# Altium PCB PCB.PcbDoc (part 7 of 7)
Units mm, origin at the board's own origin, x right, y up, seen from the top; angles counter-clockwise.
Board outline 243.2 x 142.8 mm, 4 copper layers (Top Layer, Layer 1, Layer 2, Bottom Layer), stack 0.603 mm thick; 451 components, 380 nets, 2276 pads, 1520 vias.
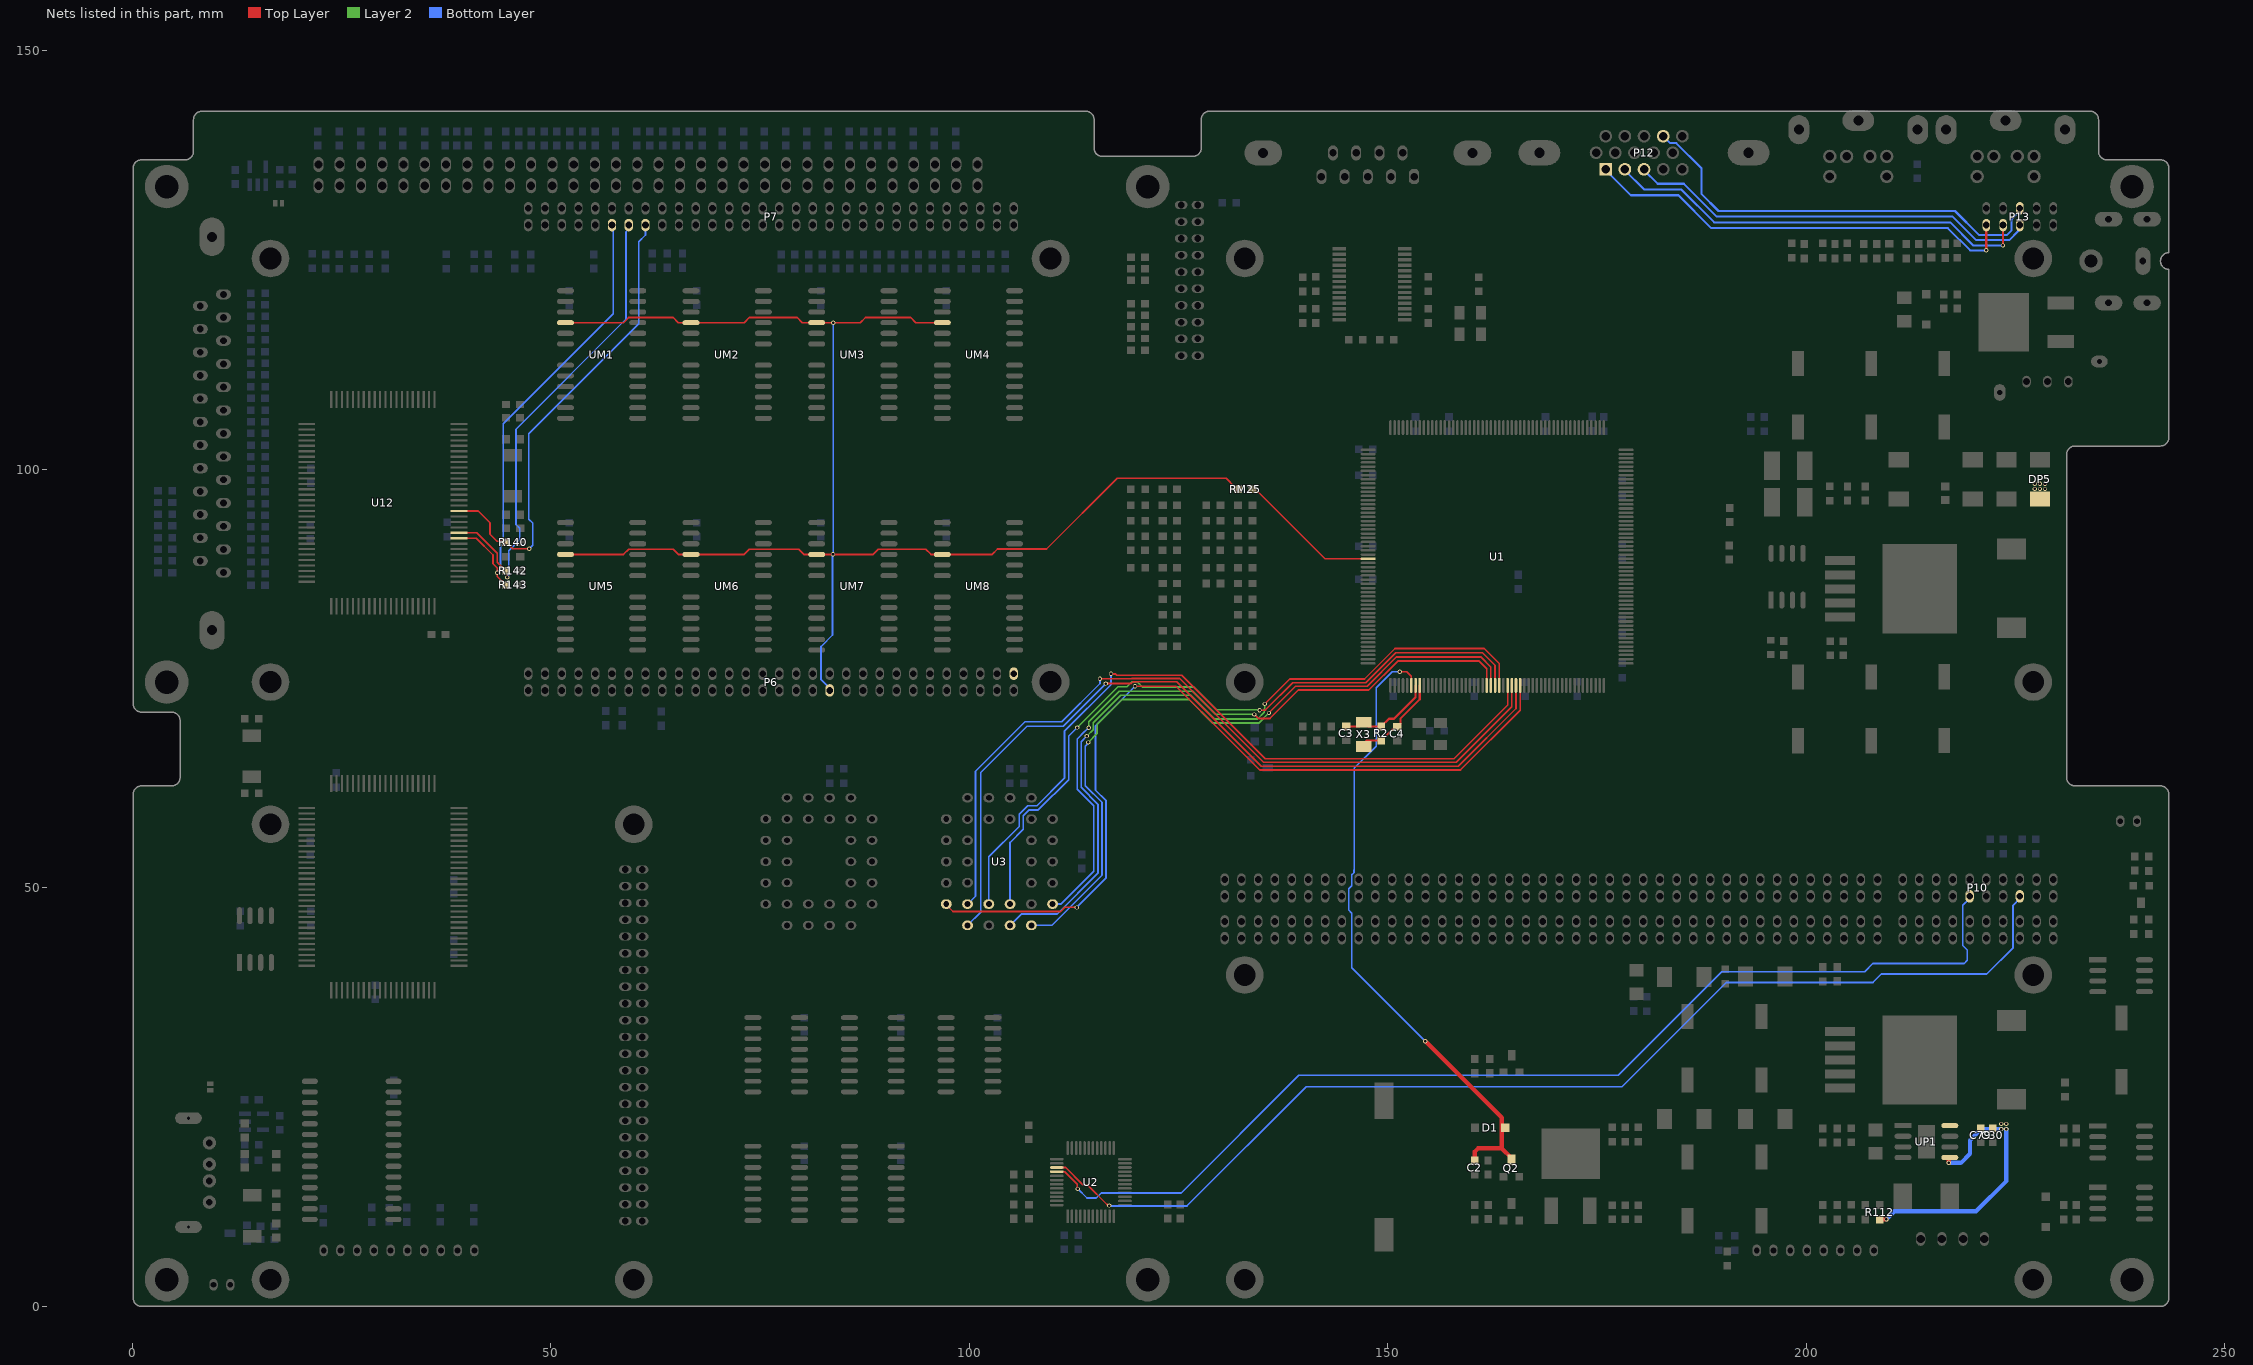
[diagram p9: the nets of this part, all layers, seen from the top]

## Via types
v1: diameter 0.508, hole 0.305, Top Layer to Bottom Layer, tented both sides, 1451 vias
v2: diameter 0.508, hole 0.3, Top Layer to Bottom Layer, 67 vias
v3: diameter 1.2, hole 1.2, Top Layer to Bottom Layer, 2 vias

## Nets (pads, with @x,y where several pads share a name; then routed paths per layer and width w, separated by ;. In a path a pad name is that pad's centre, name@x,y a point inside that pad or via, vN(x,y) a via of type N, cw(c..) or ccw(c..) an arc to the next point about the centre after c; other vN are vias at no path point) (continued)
VCHG: C30.1 C79.1 DP5.K P6.60 R112.1 UP1.5 UP1.8 | length 32.9
  Top Layer w0.508: R112.1@208.748,10.406 208.75,10.404 v1(209.561,10.404) ; v1(217.003,17.161) 217.003,17.749 217.05,17.796 UP1.5@217.13,17.796
  Bottom Layer w0.508: v1(209.561,10.404) 210.526,11.369 220.255,11.369 223.887,15.002 v1(223.887,21.199) ; v1(217.003,17.161) 218.451,17.161 219.543,18.253 219.543,19.853 220.89,21.199 v1(223.277,21.199)
  other v1: 223.277,21.809 223.887,21.809 227.29,97.678 227.9,97.678 228.51,97.678 227.29,98.287 227.9,98.287 228.51,98.287
VCMOS: C2.1 D1.K Q2.C U1.110 | length 76.6
  Top Layer w0.203: v1(151.421,75.835) 152.233,75.835 152.786,75.282 152.786,74.224 U1.110@152.805,74.206
  Top Layer w0.508: v1(154.457,31.699) 163.6,22.557 163.6,18.888 ; C2.1@160.339,17.487 C2.1@160.387,17.44 160.387,18.511 160.764,18.888 163.6,18.888 ; Q2.C@164.768,17.542 164.768,17.719 163.6,18.888
  Bottom Layer w0.203: v1(151.421,75.835) 150.506,75.835 148.601,73.93 148.601,66.945 145.985,64.328 145.985,52.187 145.96,52.162 145.96,51.848 145.695,51.583 145.695,50.268 145.314,49.887 145.314,47.363 145.686,46.991 145.686,40.471 v1(154.457,31.699)
VGA_B_OUT: P12.3 P13.5 | length 49.4
  Bottom Layer w0.254: P12.3@180.6,135.76 182.232,134.128 185.355,134.128 189.279,130.204 217.473,130.204 220.28,127.397 224.217,127.397 225.277,128.456 225.277,128.502 225.376,128.602 225.376,129.076 P13.5@225.5,129.2
VGA_G_OUT: P12.2 P13.3 | length 51.3
  Top Layer w0.254: v1(223.48,126.762) 223.49,126.771 223.49,129.19 P13.3@223.5,129.2
  Bottom Layer w0.254: P12.2@178.31,135.76 180.628,133.442 185.05,133.442 188.971,129.521 217.19,129.521 219.95,126.762 v1(223.48,126.762)
VGA_IN_EN#: P10.6 U2.3 | length 135.3
  Top Layer w0.203: U2.3@110.431,16.603 111.515,16.603 113.563,14.554 114.071,14.554 116.447,12.179 116.506,12.179 116.627,12.058 v1(116.71,12.058)
  Bottom Layer w0.203: v1@116.762,12.014 126.007,12.014 140.257,26.264 177.978,26.264 190.424,38.71 207.948,38.71 208.964,39.726 221.56,39.726 224.695,42.861 224.695,47.945 225.5,48.75 P10.6@225.5,49
VGA_R_OUT: P12.1 P13.1 | length 52.5
  Top Layer w0.254: v1(221.474,126.177) 221.487,126.19 221.487,129.187 P13.1@221.5,129.2
  Bottom Layer w0.254: P12.1@176.02,135.76 179.024,132.756 184.72,132.756 188.637,128.839 216.907,128.839 219.569,126.177 v1(221.474,126.177)
VGAOUT#/LCD: P10.12 U2.4 | length 130.4
  Top Layer w0.203: U2.4@110.431,16.103 110.45,16.084 111.398,16.084 112.895,14.587 112.895,14.105 v1(112.954,14.046)
  Bottom Layer w0.203: v1(112.954,14.046) 112.954,14.043 114.043,12.954 115.138,12.954 115.748,13.564 125.294,13.564 139.365,27.635 177.521,27.635 189.89,40.005 206.98,40.005 207.945,40.97 218.846,40.97 219.227,41.351 219.227,42.596 218.695,43.128 218.695,47.945 219.5,48.75 P10.12@219.5,49
VSYNC: P12.14 P13.6 | length 51.6
  Bottom Layer w0.254: P12.14@182.89,139.82 183.721,138.989 184.467,138.989 187.446,136.009 187.446,132.947 189.507,130.886 217.755,130.886 220.61,128.032 223.988,128.032 224.522,128.565 224.522,129.922 225.5,130.9 P13.6@225.5,131.2
WD#: P7.11 R143.1 U12.9 | length 56.5
  Top Layer w0.203: U12.9@39.026,91.779 41.09,91.779 43.09,89.779 43.09,88.741 43.599,88.231 43.599,87.694 v1@43.623,87.67 ; v1(43.599,87.67) 43.6,87.668 43.6,87.211 44.207,86.604 44.207,86.593 44.577,86.223 R143.1@44.664,86.223
  Bottom Layer w0.203: v1(43.599,87.67) 43.599,87.701 43.979,88.08 43.979,91.379 44.291,91.691 44.291,105.452 57.443,118.604 57.443,129.057 P7.11@57.3,129.2
WE#: P6.37 RM25.2 UM1.4 UM2.4 UM3.4 UM4.4 UM5.4 UM6.4 UM7.4 UM8.4 | length 177.8
  Top Layer w0.203: UM5.4@51.739,89.849 58.673,89.849 59.282,90.459 64.605,90.459 65.215,89.849 UM6.4@66.747,89.849 73.085,89.849 73.695,90.459 79.621,90.459 80.231,89.849 UM7.4@81.756,89.849 83.704,89.849 88.503,89.849 89.113,90.459 94.806,90.459 95.415,89.849 UM8.4@96.764,89.849 102.723,89.849 103.364,90.49 109.21,90.49 117.666,98.946 130.671,98.946 131.65,97.968 131.757,97.968 RM25.2@132.1,97.625 ; UM1.4@51.739,117.54 58.673,117.54 59.282,118.149 64.605,118.149 65.215,117.54 UM2.4@66.747,117.54 73.085,117.54 73.695,118.149 79.439,118.149 80.048,117.54 UM3.4@81.756,117.54 83.73,117.54 86.976,117.54 87.586,118.149 93.002,118.149 93.612,117.54 UM4.4@96.764,117.54
  Bottom Layer w0.203: P6.37@83.3,73.6 83.3,73.85 82.282,74.868 82.282,78.857 83.653,80.229 83.653,89.846 v1@83.704,89.897 ; v1(83.704,89.855) 83.748,89.9 83.748,92.28 83.73,92.299 v1(83.73,117.541)
WEJ: RM25.1 U1.79 | length 17.3
  Top Layer w0.203: RM25.1@133.8,97.625 134.143,97.282 134.545,97.282 142.491,89.336 U1.79@147.647,89.336
WG#: P7.13 R142.1 U12.10 | length 57.5
  Top Layer w0.203: U12.10@39.026,92.429 41.151,92.429 43.579,90.001 43.579,88.934 44.26,88.253 44.26,88.24 44.603,87.897 R142.1@44.641,87.897 44.791,87.747 v1(44.791,87.1)
  Bottom Layer w0.203: v1(44.791,87.1) 44.791,87.182 44.963,87.354 44.963,90.296 46.293,91.625 46.293,92.962 45.823,93.432 45.823,104.817 58.975,117.969 58.975,128.417 59.3,128.743 P7.13@59.3,129.2
WP#: P7.15 R140.1 U12.14 | length 55.7
  Top Layer w0.203: U12.14@39.026,95.029 41.32,95.029 42.734,93.615 42.734,92.243 43.564,91.413 R140.1@44.46,91.413 ; R140.1@44.641,91.296 44.679,91.296 45.459,90.516 v1(47.408,90.516)
  Bottom Layer w0.203: v1(47.408,90.516) 47.824,90.932 47.824,93.597 47.354,94.067 47.354,104.258 60.506,117.41 60.506,127.211 61.3,128.005 P7.15@61.3,129.2
XD0: U1.136 U3.13 | length 102.6
  Top Layer w0.203: U3.13@97.242,48.072 97.242,47.996 98.042,47.196 110.895,47.196 111.389,47.69 112.79,47.69 v1(112.814,47.666) ; v1(119.786,74.092) 124.685,74.092 134.677,64.101 158.663,64.101 165.805,71.242 U1.136@165.805,74.206
  Bottom Layer w0.203: v1(112.814,47.666) 112.814,47.69 116.332,51.208 116.332,60.424 115.062,61.694 115.062,69.367 v1(119.786,74.092)
XD1: U1.135 U3.14 | length 97.3
  Top Layer w0.203: v1(116.28,74.423) 119.328,74.423 119.555,74.651 124.765,74.651 134.864,64.552 158.407,64.552 165.305,71.449 U1.135@165.305,74.206
  Bottom Layer w0.203: U3.14@99.782,45.532 101.357,47.107 101.357,63.795 106.879,69.317 111.201,69.317 116.28,74.395 v1(116.28,74.423) ; v1@116.307,74.422 v1@116.459,74.422
XD2: U1.134 U3.15 | length 94.7
  Top Layer w0.203: v1(115.595,75.006) 119.372,75.006 119.397,75.032 125.114,75.032 135.143,65.003 158.151,65.003 164.805,71.656 U1.134@164.805,74.206
  Bottom Layer w0.203: U3.15@99.782,48.072 100.738,49.028 100.738,63.937 106.65,69.85 111.023,69.85 115.595,74.422 v1(115.595,75.006)
XD3: U1.133 U3.17 | length 90.8
  Top Layer w0.203: v1(116.916,75.59) 116.944,75.562 117.475,75.562 117.625,75.413 125.371,75.413 135.33,65.454 157.906,65.454 164.305,71.853 U1.133@164.305,74.206
  Bottom Layer w0.203: U3.17@102.322,48.072 102.322,53.711 105.955,57.343 105.955,58.791 106.981,59.818 108.078,59.818 111.354,63.094 111.354,68.707 116.916,74.27 v1(116.916,75.59)
XD4: U1.131 U3.18 | length 90.9
  Top Layer w0.203: v1(135.28,71.984) 138.268,74.971 147.208,74.971 150.842,78.605 161.516,78.605 163.305,76.816 U1.131@163.305,74.206
  Layer 2 w0.203: v1(114.021,68.148) 114.049,68.148 114.808,68.907 114.808,69.748 118.085,73.025 126.467,73.025 129.311,70.18 134.417,70.18 135.23,70.993 135.23,71.374 135.28,71.425 v1(135.28,71.984)
  Bottom Layer w0.203: U3.18@104.862,45.532 106.209,46.879 110.476,46.879 115.354,51.757 115.354,60.019 113.36,62.013 113.36,67.488 v1(114.021,68.148)
XD5: U1.130 U3.19 | length 84.5
  Top Layer w0.203: v1(134.671,71.247) 135.328,71.247 135.557,71.476 135.563,71.476 138.617,74.53 147.373,74.53 150.947,78.105 161.309,78.105 162.805,76.609 U1.130@162.805,74.206
  Layer 2 w0.203: v1(112.878,69.164) 117.754,74.041 118.821,74.041 119.431,74.651 120.04,74.651 120.675,74.016 126.873,74.016 129.591,71.298 134.62,71.298 v1(134.671,71.247)
  Bottom Layer w0.203: U3.19@104.862,48.072 104.862,55.433 106.448,57.018 106.448,58.628 107.144,59.325 108.241,59.325 111.862,62.946 111.862,68.148 v1(112.878,69.164)
XD6: U1.129 U3.20 | length 85.8
  Top Layer w0.203: v1(135.788,70.917) 138.961,74.09 147.517,74.09 151.032,77.605 161.102,77.605 162.305,76.402 U1.129@162.305,74.206
  Layer 2 w0.203: v1(114.198,67.386) 115.291,68.478 115.291,69.545 118.262,72.517 126.238,72.517 129.057,69.698 134.569,69.698 v1(135.788,70.917)
  Bottom Layer w0.203: U3.20@107.402,45.532 109.866,45.532 115.843,51.509 115.843,60.221 113.843,62.222 113.843,66.952 114.198,67.307 v1(114.198,67.386)
XD7: U1.128 U3.21 | length 81.4
  Top Layer w0.203: v1(134.036,70.739) 134.518,70.256 135.918,70.256 139.311,73.649 147.711,73.649 151.167,77.105 160.895,77.105 161.805,76.195 U1.128@161.805,74.206
  Layer 2 w0.203: v1(114.249,69.139) 114.249,69.85 117.907,73.508 126.67,73.508 129.413,70.764 134.01,70.764 v1(134.036,70.739)
  Bottom Layer w0.203: U3.21@109.942,48.072 110.933,48.072 114.865,52.005 114.865,59.816 112.878,61.804 112.878,67.795 113.792,68.709 113.82,68.709 v1(114.249,69.139)
XTAL1: C3.1 R2.2 U1.111 X3.1 | length 11.6
  Top Layer w0.254: C3.1@145.013,69.305 146.613,69.305 X3.1@147.113,69.805 147.613,69.305 R2.2@149.213,69.305 150.129,70.221 150.735,70.221 153.305,72.791 U1.111@153.305,74.206
XTAL2: C4.2 R2.1 U1.112 X3.2 | length 10.9
  Top Layer w0.254: X3.2@147.113,67.265 147.453,67.605 R2.1@149.213,67.605 149.213,67.643 150.482,68.913 150.77,68.913 C4.2@151.113,69.256 151.151,69.256 151.494,69.598 151.494,70.218 153.805,72.529 U1.112@153.805,74.206
pads on no net: P1.2 P1.6 P2.2 P2.6 P3.20 P3.21 P3.28 P3.29 P3.34 P3.44 P4.12 P4.13 P4.14 P5.63 P6.4 P6.5 P6.6 P6.8 P7.53 P12.4 P12.9 P12.11 P13.10 SP1.1 U1.33 U1.35 U1.36 U1.37 U1.41 U1.42 U1.43 U1.77 U1.78 U1.109 U1.114 U1.115 U1.116 U1.120 U1.124 U1.126 U1.127 U2.2 U2.21 U2.22 U2.23 U2.33 U2.34 U2.35 U2.36 U2.37 U2.38 U2.39 U2.40 U2.48 U3.1 U3.2 U3.30 U4.9 U4.10 U4.13 U4.14 U4.15 U6.7 U6.9 U6.10 U6.12 U6.13 U6.14 U6.15 U7.9 U7.10 U7.11 U7.12 U7.13 U7.14 U7.15 U9.1 U9.6 U9.7 U9.24 U9.25 U9.26 U10.1 U10.2 U10.30 U12.18 U12.19 U12.86 U12.87 U12.90 U12.92 U12.93 U13.21 U13.28 U18.5 U18.6 U18.7 U18.9 U18.10 U18.11 U19.4 U19.5 U19.10 U19.11 U19.12 UN1.48 UN1.49 UN1.53 UN1.54 UN1.55 UN1.56 UN1.60 UN1.63 UN1.64 UN1.66 UN1.67 UN1.68 UN1.69 UN1.71 UN1.72 UN1.73 UN1.74 UN1.75 UN1.80 UN1.81 UN1.82 UN1.84 UN1.85 UN2.6 UN2.7 X1.1 X2.1

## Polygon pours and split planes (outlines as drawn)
GND on Top Layer "NONET_L-01_P-001" (solid, remove dead copper, pour order 22): 231.558,142.789 6.336,142.789 0.087,136.541 0.087,1.133 0.9,0.32 242.657,0.32 243.115,0.778 243.115,139.792 240.067,142.84
+12V on Top Layer "NONET_L-01_P-001" (solid, remove dead copper, pour order 19): 227.468,52.949 222.849,52.949 222.287,52.386 222.287,42.187 218.124,38.024 210.134,38.024 209.866,37.756 209.866,36.541 210.145,36.261 222.287,36.261 224.344,38.319 224.344,40.783 225.919,42.357 227.519,42.357 228.535,43.373 228.535,51.882
NetL1_2 on Top Layer "NONET_L-01_P-001" (solid, remove dead copper, pour order 2): 216.216,20.92 216.038,20.742 216.038,19.929 216.165,19.802 218.197,19.802 218.705,19.294 218.705,17.44 217.867,16.602 216.419,16.602 215.937,16.119 215.937,11.446 216.064,11.319 219.721,11.319 219.975,11.573 219.975,20.412 219.467,20.92
IPSOUT on Top Layer "NONET_L-01_P-001" (solid, remove dead copper, pour order 1): 235.622,41.926 232.751,41.926 231.812,40.986 231.812,26.101 231.354,25.644 228.306,25.644 227.671,26.279 222.896,26.279 222.439,25.822 222.439,23.561 223.201,22.799 237.882,22.799 238.949,21.733 238.949,17.465 239.33,17.084 241.21,17.084 241.54,17.415 241.54,23.307 240.041,24.806 236.638,24.806 236.13,25.314 236.13,31.969 236.561,32.401 238.187,32.401 238.644,32.858 238.644,35.703 238.212,36.134 236.46,36.134 236.053,36.541 236.053,41.621 235.774,41.9
NetDP3_A on Top Layer "NONET_L-01_P-001" (solid, remove dead copper, pour order 0): 225.817,121.072 225.792,121.047 220.407,121.047 219.899,120.539 219.899,108.956 218.451,107.508 218.451,100.32 218.756,100.015 225.208,100.015 225.462,100.269 225.462,103.216 227.138,104.892 227.138,120.589 226.63,121.097
GND on Bottom Layer "NONET_L-01_P-001" (solid, remove dead copper, pour order 24): 234.479,142.637 7.504,142.637 0.316,135.448 0.316,0.701 0.773,0.244 242.81,0.244 243.216,0.651 243.216,137.684 238.314,142.586
-12V on Bottom Layer "NONET_L-01_P-001" (solid, remove dead copper, pour order 20): 228.305,49.8 227.722,49.8 226.732,49.8 226.3,49.368 226.3,43.577 226.732,43.145 228.651,43.145 228.651,49.454
+12V on Bottom Layer "NONET_L-01_P-001" (solid, remove dead copper, pour order 21): 174.662,129.175 176.338,129.175 181.951,123.561 207.301,123.561 223.353,107.508 223.353,79.721 221.804,78.171 221.804,70.297 225.817,66.284 225.817,61.56 230.135,57.242 230.135,53.529 228.498,51.892 228.498,50.724 227.863,50.089 226.95,50.089 226.427,50.612 226.427,51.882 225.97,52.34 225.131,52.34 224.827,52.644 224.827,53.991 225.335,54.499 227.976,54.499 228.205,54.727 228.205,56.327 223.76,60.772 223.76,65.446 219.442,69.764 219.442,80.534 221.067,82.159 221.067,105.807 205.751,121.123 180.91,121.123 174.306,127.727 174.306,128.819
+12R on Bottom Layer "NONET_L-01_P-001" (solid, remove dead copper, pour order 11): 220.407,98.542 218.807,98.542 218.451,98.187 218.451,85.004 206.437,72.99 202.043,72.99 201.662,72.609 201.662,70.297 202.119,69.84 208.19,69.84 220.61,82.261 220.61,98.339
ACIN on Bottom Layer "NONET_L-01_P-001" (solid, remove dead copper, pour order 4): 235.037,126.863 231.888,126.863 231.1,126.075 231.1,117.211 229.373,115.484 229.373,109.871 226.681,107.178 226.681,101.895 226.833,101.743 228.916,101.743 229.195,102.022 229.272,102.022 229.272,104.537 232.447,107.712 232.447,114.036 233.717,115.306 233.717,121.428 235.495,123.206 235.495,126.406
+5V on Layer 2 "NONET_L-01_P-001" (solid, remove dead copper, pour order 16): 234.199,142.408 98.208,142.408 98.208,129.022 97.293,128.108 38.365,128.108 34.962,124.704 17.74,124.704 2.907,109.871 2.907,14.163 11.568,5.502 203.999,5.502 227.367,28.87 227.367,95.926 233.818,102.378 242.734,102.378 243.648,103.292 243.648,140.173 241.413,142.408
VCHG on Layer 2 "NONET_L-01_P-001" (solid, remove dead copper, pour order 8): 214.794,102.606 209.002,96.815 185.965,96.815 174.128,84.979 110.552,84.979 104.38,78.806 104.38,75.174 104.939,74.615 106.336,74.615 106.793,75.073 106.793,77.689 111.162,82.058 176.998,82.058 188.733,93.792 210.476,93.792 216.368,99.685 225.106,99.685 226.122,98.669 226.122,80.864 223.684,78.425 223.684,72.126 227.417,68.392 227.417,62.042 236.866,52.594 236.866,25.619 234.428,23.18 223.48,23.18 222.871,22.571 222.871,20.132 223.379,19.624 242.073,19.624 242.886,20.437 242.886,61.077 242.099,61.865 231.786,61.865 230.821,62.83 230.821,100.854 229.068,102.606
-12V on Layer 2 "NONET_L-01_P-001" (solid, remove dead copper, pour order 7): 37.654,134.813 37.629,134.788 36.003,134.788 35.724,134.509 35.724,132.324 31.964,128.565 26.046,128.565 18.477,120.996 13.676,120.996 11.771,122.901 5.244,122.901 3.999,121.656 3.999,82.337 8.927,77.409 8.927,59.782 7.631,58.486 4.71,58.486 3.872,57.648 3.872,9.591 5.574,7.89 19.137,7.89 23.506,3.521 53.859,3.521 57.288,6.95 62.851,6.95 66.204,3.597 114.311,3.597 118.502,7.788 135.292,7.788 139.864,3.216 175.906,3.216 177.227,4.537 177.227,10.836 178.268,11.877 178.268,16.145 177.887,16.526 175.017,16.526 174.204,15.713 174.204,7.28 173.087,6.162 142.048,6.162 136.79,11.42 117.156,11.42 112.66,6.924 68.032,6.924 65.213,9.744 22.135,9.744 20.89,10.988 11.873,10.988 11.086,11.776 11.086,21.428 6.717,25.797 6.717,52.695 11.314,57.293 11.314,76.698 12.533,77.917 12.533,116.475 13.727,117.668 20.357,117.668 28.129,125.441 34.25,125.441 38.314,129.505 38.314,134.331 37.832,134.813
IPSOUT on Layer 2 "NONET_L-01_P-001" (solid, remove dead copper, pour order 9): 223.506,98.847 224.979,98.847 225.589,98.237 225.589,81.016 223.201,78.629 223.201,71.923 226.986,68.138 226.986,61.814 236.46,52.34 236.46,25.797 234.402,23.739 224.115,23.739 223.633,24.222 223.633,25.949 224.141,26.457 230.161,26.457 232.142,28.438 232.142,45.05 230.186,47.006 221.296,47.006 220.763,46.472 220.763,45.147 220.396,44.78 218.669,44.78 218.248,45.201 218.248,47.336 219.188,48.276 225.868,48.276 226.173,48.58 226.173,54.93 223.506,57.597 223.506,65.294 216.953,71.847 216.953,78.425 222.769,84.242 222.769,98.542 223.074,98.847
+12V on Layer 2 "NONET_L-01_P-001" (solid, remove dead copper, pour order 12): 177.557,38.192 177.608,38.243 179.284,38.243 179.615,37.912 182.155,37.912 182.917,38.674 210.501,38.674 211.441,37.735 211.441,36.287 210.73,35.576 177.684,35.576 177.456,35.804 177.456,37.989
VCC_ISA on Layer 2 "NONET_L-01_P-001" (solid, remove dead copper, pour order 5): 32.345,138.674 26.808,138.674 26.046,137.912 26.046,133.162 26.707,132.502 28.332,132.502 28.789,132.959 28.789,134.483 29.348,135.042 91.35,135.042 91.654,134.737 91.654,133.137 92.086,132.705 94.093,132.705 94.804,133.416 94.804,137.811 93.94,138.674
+12V on Layer 2 "NONET_L-01_P-001" (solid, remove dead copper, pour order 15): 104.989,132.07 104.532,131.613 104.532,127.498 105.472,126.558 111.949,126.558 114.032,124.476 124.116,124.476 125.309,123.282 129.45,123.282 131.024,121.707 136.663,121.707 141.794,126.838 175.119,126.838 175.881,127.6 175.881,128.971 175.398,129.454 131.837,129.454 129.551,127.168 115.937,127.168 113.727,129.378 107.25,129.378 106.742,129.886 106.742,131.867 106.539,132.07
VBAT on Layer 2 "NONET_L-01_P-001" (solid, remove dead copper, pour order 14): 221.956,22.342 211.847,22.342 208.621,19.116 205.523,19.116 191.629,5.223 191.629,0.854 192.086,0.397 242.276,0.397 243.038,1.159 243.038,17.973 241.819,19.193 223.176,19.193 222.49,19.878 222.49,22.063
-12V on Layer 2 "NONET_L-01_P-001" (solid, remove dead copper, pour order 13): 229.475,44.999 227.367,44.999 226.706,44.339 226.706,42.815 227.163,42.357 227.163,42.23 228.383,42.23 229.449,41.164 229.449,38.547 227.925,37.023 225.385,37.023 222.21,33.848 214.514,26.152 205.599,26.152 191.045,11.598 182.155,11.598 181.469,10.912 181.469,0.955 182.028,0.397 190.689,0.397 191.299,1.006 191.299,5.527 205.345,19.574 208.545,19.574 211.669,22.698 222.414,22.698 226.655,26.94 229.932,26.94 231.583,28.591 231.583,44.516 231.126,44.974
+12R on Layer 2 "NONET_L-01_P-001" (solid, remove dead copper, pour order 10): 203.287,72.253 193.661,72.253 179.107,57.699 179.107,39.03 179.716,38.42 182.028,38.42 182.485,38.878 182.485,41.697 183.653,42.865 183.653,57.216 195.642,69.205 203.389,69.205 203.592,69.408 203.592,71.948
-5V on Layer 2 "NONET_L-01_P-001" (solid, remove dead copper, pour order 6): 95.39,141.8 22.517,141.8 19.62,138.903 19.62,132.959 17.436,130.775 1.789,130.775 0.621,129.606 0.621,1.235 1.688,0.168 180.046,0.168 181.164,1.286 181.164,11.522 181.672,12.03 190.74,12.03 205.37,26.66 214.26,26.66 224.547,36.947 224.547,40.3 226.02,41.773 226.02,44.593 225.843,44.77 225.843,44.796 224.877,44.796 224.547,44.466 224.547,43.5 222.185,41.138 222.185,38.293 214.768,30.877 205.396,30.877 191.197,16.678 181.164,16.678 178.446,13.96 178.446,11.471 177.557,10.582 177.557,3.851 176.49,2.784 139.635,2.784 134.961,7.458 118.655,7.458 114.387,3.191 66,3.191 62.597,6.594 57.441,6.594 54.037,3.191 23.379,3.191 18.934,7.636 5.447,7.636 3.542,9.541 3.542,57.902 4.431,58.791 7.428,58.791 8.647,60.01 8.647,77.181 3.745,82.083 3.745,121.732 5.167,123.155 11.949,123.155 13.829,121.275 18.223,121.275 25.843,128.895 31.71,128.895 33.209,130.394 33.209,134.255 32.676,134.788 31.279,134.788 30.821,134.331 30.821,132.756 29.983,131.918 26.199,131.918 24.141,133.975 24.141,136.795 26.453,139.106 94.296,139.106 96.277,137.125 96.277,131.664 97.573,130.368 99.681,130.368 100.036,130.724 100.036,138.192 96.428,141.8
GND on Layer 1 "NONET_L-01_P-001" (solid, remove dead copper, pour order 23): 7.682,142.637 0.392,135.347 0.392,0.701 0.951,0.143 242.683,0.143 243.572,1.032 243.572,137.861 238.797,142.637
+12V on Layer 1 "NONET_L-01_P-001" (solid, remove dead copper, pour order 18): 42.023,135.042 41.489,134.509 41.489,128.032 44.41,125.111 104.329,125.111 105.777,126.558 105.777,131.842 105.472,132.146 104.634,132.146 104.38,131.892 104.38,128.438 103.465,127.524 45.274,127.524 43.496,129.302 43.496,134.763 43.217,135.042

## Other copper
Top Layer:
  rectangle net GND: 210.145,99.558 211.898,102.479
  rectangle net GND: 209.231,100.549 212.736,101.692
  rectangle net GND: 202.424,88.255 205.497,90.44
  rectangle net GND: 237.501,25.797 239.152,27.854
  rectangle net GND: 167.956,10.455 171.207,12.487
  rectangle net GND: 212.965,17.008 215.632,22.393
  rectangle net GND: 184.72,16.729 187.006,18.989
  rectangle net GND: 196.785,20.742 198.182,24.044
  rectangle net GND: 195.566,21.783 197.09,23.358
  rectangle net GND: 183.907,25.898 196.556,28.083
  rectangle net GND: 202.754,31.969 205.243,34.052
  rectangle net GND: 46.468,103.343 47.331,103.927
  rectangle net VCC1: 198.842,94.402 199.528,102.53
  pour cut-out: 157.769,101.485 157.769,100.037 158.734,100.037 158.734,101.485
  pour cut-out: 208.899,17.716 208.899,16.268 209.864,16.268 209.864,17.716
  pour cut-out: 217.533,18.94 216.085,18.94 216.085,17.975 217.533,17.975
  pour cut-out: 235.948,11.727 234.5,11.727 234.5,10.762 235.948,10.762
  pour cut-out: 231.503,22.674 230.055,22.674 230.055,21.709 231.503,21.709
  pour cut-out: 231.529,20.998 230.081,20.998 230.081,20.033 231.529,20.033
  pour cut-out: 141.486,68.293 140.038,68.293 140.038,67.327 141.486,67.327
  pour cut-out: 143.086,68.318 141.638,68.318 141.638,67.353 143.086,67.353
  pour cut-out: 141.409,69.588 139.962,69.588 139.962,68.623 141.409,68.623
  pour cut-out: 143.289,69.537 141.841,69.537 141.841,68.572 143.289,68.572
  pour cut-out: 144.457,69.563 143.01,69.563 143.01,68.597 144.457,68.597
  pour cut-out: 147.003,67.761 147.003,69.209 146.038,69.209 146.038,67.761
  pour cut-out: 13.932,9.16 13.932,12.516 12.967,12.516 12.967,9.16
  pour cut-out: 104.61,120.822 104.61,122.269 103.645,122.269 103.645,120.822
  pour cut-out: 107.379,120.999 107.379,122.447 106.414,122.447 106.414,120.999
  pour cut-out: 125.743,127.654 125.743,129.102 124.778,129.102 124.778,127.654
  pour cut-out: 125.032,127.019 125.032,128.467 124.067,128.467 124.067,127.019
  pour cut-out: 141.73,117.692 141.73,119.14 140.765,119.14 140.765,117.692
  pour cut-out: 141.186,118.688 141.186,120.136 140.221,120.136 140.221,118.688
  pour cut-out: 209.334,125.419 209.334,126.867 208.369,126.867 208.369,125.419
  pour cut-out: 208.115,124.098 208.115,125.546 207.15,125.546 207.15,124.098
  pour cut-out: 214.745,125.571 214.745,127.019 213.779,127.019 213.779,125.571
  pour cut-out: 196.66,90.215 196.66,91.662 195.695,91.662 195.695,90.215
  pour cut-out: 213.17,96.285 213.17,97.733 212.205,97.733 212.205,96.285
  pour cut-out: 136.64,69.59 136.64,71.038 135.674,71.038 135.674,69.59
  pour cut-out: 145.758,89.834 145.758,91.281 144.793,91.281 144.793,89.834
  pour cut-out: 124.448,96.946 124.448,98.393 123.482,98.393 123.482,96.946
  pour cut-out: 68.669,91.307 68.669,92.755 67.704,92.755 67.704,91.307
  pour cut-out: 74.382,93.046 74.382,94.494 73.416,94.494 73.416,93.046
  pour cut-out: 51.677,79.772 51.677,84.652 50.711,84.652 50.711,79.772
  pour cut-out: 51.727,87.802 51.727,89.249 50.762,89.249 50.762,87.802
  pour cut-out: 45.809,85.541 45.809,86.989 44.844,86.989 44.844,85.541
  pour cut-out: 45.377,92.577 45.377,94.025 44.412,94.025 44.412,92.577
  pour cut-out: 46.8,97.171 46.8,100.857 45.835,100.857 45.835,97.171
  pour cut-out: 54.598,118.815 54.598,120.263 53.632,120.263 53.632,118.815
  pour cut-out: 51.651,114.722 51.651,118.51 50.686,118.51 50.686,114.722
  pour cut-out: 68.898,118.891 68.898,120.339 67.933,120.339 67.933,118.891
  pour cut-out: 82.817,122.219 82.817,123.666 81.852,123.666 81.852,122.219
  pour cut-out: 106.439,107.635 106.439,112.567 105.474,112.567 105.474,107.635
  pour cut-out: 117.439,121.477 118.887,121.477 118.887,122.442 117.439,122.442
  pour cut-out: 115.915,123.102 117.363,123.102 117.363,124.067 115.915,124.067
  pour cut-out: 119.467,113.579 120.915,113.579 120.915,114.544 119.467,114.544
  region net +5V: 14.87,137.734 14.692,137.912 13.956,137.912 13.346,137.303 13.346,136.668 20.509,129.505 20.509,123.866 22.287,122.088 22.287,118.888 22.49,118.684 22.922,118.684 23.481,119.243 23.481,123.409 22.109,124.78 22.109,130.495
  region net +12V: 177.735,38.624 177.532,38.42 177.532,36.439 177.684,36.287 180.91,36.287 181.037,36.414 181.037,37.862 180.275,38.624
  region net +12R: 178.903,40.986 178.802,40.884 178.802,39.335 178.929,39.208 180.427,39.208 181.57,38.065 183.933,38.065 184.06,38.192 184.06,40.681 183.755,40.986
  region net -5V: 173.265,14.316 173.061,14.113 173.061,9.871 173.239,9.693 174.992,9.693 175.17,9.871 175.17,11.217 175.551,11.598 180.529,11.598 180.808,11.877 180.808,13.757 180.25,14.316
  region net -12V: 183.856,23.866 181.901,23.866 181.596,23.561 181.596,20.92 181.012,20.336 176.262,20.336 175.271,21.326 168.362,21.326 168.134,21.098 168.134,15.281 168.54,14.875 180.427,14.875 181.342,13.96 181.342,8.88 181.901,8.321 186.32,8.321 186.6,8.601 186.6,12.411 185.812,13.198 184.644,13.198 184.263,13.579 184.263,23.638 184.034,23.866
  region net NetQ5_1: 237.679,21.987 238.263,21.402 238.263,11.7 238.009,11.446 233.691,11.446 233.437,11.7 233.437,16.551 233.894,17.008 235.825,17.008 236.104,17.288 236.104,18.38 235.926,18.558 233.818,18.558 233.31,19.066 233.31,21.707 233.59,21.987
  region net VBAT: 239.33,16.043 238.974,15.687 238.974,10.201 239.228,9.947 241.565,9.947 241.768,10.15 241.768,15.687 241.413,16.043
  region net NetL1_1: 210.653,16.17 210.349,15.865 210.349,11.42 210.425,11.344 212.66,11.344 212.762,11.446 212.762,15.992 212.584,16.17
  region net VBAT: 206.539,19.523 206.208,19.193 206.208,17.338 206.361,17.186 208.901,17.186 210.323,18.608 212.381,18.608 212.584,18.812 212.584,19.396 212.457,19.523
  region net NetL1_1: 206.361,21.91 206.208,21.758 206.208,20.31 206.564,19.955 212.406,19.955 212.584,20.132 212.584,20.488 212.355,20.717 210.298,20.717 209.104,21.91
  region net VCHG: 216.318,22.596 216.038,22.317 216.038,21.428 216.191,21.275 219.848,21.275 220.28,20.844 224.115,20.844 224.242,20.971 224.242,22.012 223.988,22.266 222.896,22.266 222.566,22.596
  region net DCDC12V: 186.676,40.681 186.371,40.376 186.371,37.531 184.923,36.084 184.923,33.061 185.457,32.528 195.134,32.528 195.388,32.782 195.388,36.109 194.22,37.277 194.22,40.706 194.118,40.808 191.832,40.808 191.578,40.554 191.578,39.462 191.299,39.182 189.14,39.182 188.886,39.436 188.886,40.554 188.759,40.681
  region net NetCP7_2: 193.407,23.663 193.381,23.688 186.879,23.688 186.727,23.536 186.727,20.615 187.26,20.082 187.971,19.37 187.971,9.845 189.317,8.499 195.286,8.499 195.464,8.677 195.464,15.002 195.032,15.433 193.534,15.433 193.127,15.84 193.127,19.802 194.042,20.717 194.042,23.434 193.813,23.663
  region net NetCP7_1: 199.604,40.783 196.683,40.783 196.429,40.529 196.429,37.354 197.572,36.211 197.572,25.492 198.868,24.196 198.868,20.361 198.36,19.853 194.22,19.853 193.737,19.37 193.737,16.297 193.966,16.068 199.528,16.068 201.078,17.618 201.078,22.698 201.636,23.257 201.636,28.438 202.043,28.845 208.063,28.845 208.494,28.413 208.494,24.273 208.952,23.815 218.756,23.815 219.213,24.273 219.213,30.521 220.763,32.07 226.02,32.07 226.452,32.502 226.452,35.499 226.097,35.855 208.825,35.855 207.478,34.509 207.478,30.826 206.793,30.14 201.636,30.14 201.078,30.699 201.078,36.49 199.884,37.684 199.884,40.579 199.681,40.783
  region net IPSOUT: 207.783,28.362 202.246,28.362 202.144,28.26 202.144,27.219 202.221,27.143 206.005,27.143 206.589,26.559 207.834,26.559 207.936,26.66 207.936,28.235 207.859,28.311
  region net NetPP2_2: 238.314,41.824 238.085,41.595 238.085,37.404 238.314,37.176 241.311,37.176 241.489,37.354 241.489,41.646 241.311,41.824
  region net VCHG: 226.947,98.567 226.719,98.338 226.719,96.535 229.094,96.535 229.094,98.376 228.903,98.567
  region net +12R: 218.921,98.567 218.692,98.338 218.692,96.535 221.067,96.535 221.067,98.376 220.877,98.567
  region net IPSOUT: 222.934,98.567 222.706,98.338 222.706,96.535 225.081,96.535 225.081,98.376 224.89,98.567
  region net IPSOUT: 205.523,83.023 201.179,83.023 198.715,80.559 198.715,77.257 198.157,76.698 198.157,73.117 198.512,72.761 218.172,72.761 218.527,73.117 218.527,76.927 218.146,77.308 207.478,77.308 206.539,78.248 202.246,78.248 201.941,78.552 201.941,80.483 202.475,81.016 205.65,81.016 205.904,81.27 205.904,82.845 205.726,83.023
  region net +5V: 193.762,102.251 193.483,101.971 193.483,94.504 193.661,94.326 196.785,94.326 196.861,94.402 196.861,102.149 196.76,102.251
  region net VCC1: 199.173,108.169 198.106,107.102 198.106,102.962 199.096,101.971 199.096,89.068 199.35,88.814 200.874,88.814 201.128,89.068 201.128,94.021 201.992,94.885 203.237,94.885 203.567,95.215 203.567,96.536 203.338,96.764 202.297,96.764 201.789,97.272 201.789,101.412 203.211,102.835 212.99,102.835 213.346,102.479 213.295,102.428 213.295,92.268 213.803,91.76 218.324,91.76 219.747,90.338 219.747,89.322 220.128,88.941 226.173,88.941 226.452,89.22 226.452,92.345 225.081,93.716 222.185,93.716 221.245,94.656 217.943,94.656 217.232,95.367 217.232,96.688 217.105,96.815 215.937,96.815 215.505,97.247 215.505,98.999 217.384,100.879 217.384,107.686 216.902,108.169
  region net NetDP6_K: 209.206,97.552 208.367,96.713 208.367,87.598 207.094,86.325 202.271,86.325 202.17,86.223 202.17,85.106 202.221,85.055 207.097,85.055 208.113,84.039 208.113,80.711 209.079,79.746 226.097,79.746 226.351,80 226.351,83.912 225.97,84.293 219.797,84.293 219.188,84.902 219.188,89.855 217.918,91.125 213.374,91.125 212.635,91.865 212.635,97.171 212.254,97.552
  region net ACIN: 226.947,103.267 226.719,103.038 226.719,101.235 229.094,101.235 229.094,103.076 228.903,103.267
  region net ACIN: 234.682,126.406 232.751,126.406 228.662,122.317 228.662,119.446 228.84,119.269 232.269,119.269 232.396,119.396 232.396,120.818 235.495,123.917 235.495,125.619 234.783,126.33
Bottom Layer:
  rectangle net +5V: 171.995,7.001 173.392,7.864
  rectangle net +5V: 13.727,135.423 16.191,137.557
  region net +5V: 23.343,124.485 21.107,124.485 21.057,124.435 21.057,123.647 22.327,122.377 22.327,118.821 22.53,118.618 23.19,118.618 23.495,118.923 23.495,124.282
  region net +5V: 195.174,105.004 192.913,105.004 192.888,104.978 192.888,100.762 193.421,100.228 194.869,100.228 195.047,100.406 195.047,103.53 195.428,103.911 195.428,104.902 195.351,104.978
  pour cut-out: 135.192,69.45 135.192,68.002 134.227,68.002 134.227,69.45
  pour cut-out: 43.139,139.364 45.501,139.364 45.501,138.653 43.139,138.653
  pour cut-out: 61.712,133.57 61.712,131.208 61,131.208 61,133.57
  pour cut-out: 130.927,126.636 130.927,124.274 130.215,124.274 130.215,126.636
  pour cut-out: 135.778,126.662 135.778,124.299 135.067,124.299 135.067,126.662
  pour cut-out: 181.699,139.128 179.337,139.128 179.337,139.839 181.699,139.839
  pour cut-out: 178.397,135.927 176.035,135.927 176.035,136.638 178.397,136.638
  pour cut-out: 180.886,135.8 178.524,135.8 178.524,136.511 180.886,136.511
  pour cut-out: 229.476,128.282 227.114,128.282 227.114,128.993 229.476,128.993
  pour cut-out: 227.876,128.307 225.514,128.307 225.514,129.018 227.876,129.018
  pour cut-out: 224.574,130.923 222.212,130.923 222.212,131.635 224.574,131.635
  pour cut-out: 203.309,35.803 203.309,38.165 204.02,38.165 204.02,35.803
  pour cut-out: 171.711,38.774 171.711,41.137 172.423,41.137 172.423,38.774
  pour cut-out: 156.575,37.408 158.937,37.408 158.937,36.697 156.575,36.697
  pour cut-out: 131.197,42.281 133.559,42.281 133.559,41.569 131.197,41.569
  pour cut-out: 79.385,57.652 81.747,57.652 81.747,56.941 79.385,56.941
  pour cut-out: 75.194,121.66 77.556,121.66 77.556,120.949 75.194,120.949
  pour cut-out: 80.07,125.749 82.433,125.749 82.433,125.038 80.07,125.038
  pour cut-out: 85.201,139.288 87.563,139.288 87.563,138.576 85.201,138.576
  pour cut-out: 95.742,136.087 98.104,136.087 98.104,135.376 95.742,135.376
  pour cut-out: 88.376,139.821 90.738,139.821 90.738,139.11 88.376,139.11
  pour cut-out: 68.031,139.364 86.168,139.364 86.168,138.653 68.031,138.653
  pour cut-out: 60.919,139.161 63.281,139.161 63.281,138.449 60.919,138.449
  pour cut-out: 57.998,138.475 60.36,138.475 60.36,137.764 57.998,137.764
  pour cut-out: 55.128,139.313 57.49,139.313 57.49,138.602 55.128,138.602
  pour cut-out: 65.084,139.44 67.447,139.44 67.447,138.729 65.084,138.729
  pour cut-out: 62.417,139.364 64.78,139.364 64.78,138.653 62.417,138.653
  pour cut-out: 52.969,139.389 55.331,139.389 55.331,138.678 52.969,138.678
  pour cut-out: 50.962,139.389 53.324,139.389 53.324,138.678 50.962,138.678
  pour cut-out: 47.89,139.411 50.252,139.411 50.252,138.7 47.89,138.7
  region net +12V: 177.633,38.166 177.659,38.192 178.548,38.192 178.929,37.811 181.215,37.811 181.494,37.531 181.494,36.566 181.291,36.363 177.557,36.363 177.456,36.465 177.456,38.065
  region net +5V: 221.702,54.524 221.525,54.346 221.525,52.263 221.067,51.806 221.067,43.602 221.347,43.323 223.633,43.323 223.938,43.627 223.938,54.473 223.887,54.524
  region net IPSOUT: 225.843,28.489 228.433,25.898 228.433,23.815 228.052,23.434 226.3,23.434 223.557,26.178 206.894,26.178 206.462,26.609 206.462,28.235 206.716,28.489
  region net VCC_ISA: 15.937,134.661 19.569,134.661 19.849,134.382 19.849,132.934 20.534,132.248 25.868,132.248 26.503,132.883 26.503,134.509 26.859,134.864 26.91,134.813 27.672,134.813 27.926,134.559 27.926,128.132 29.947,126.111 29.947,125.4 29.657,125.111 26.224,125.111 26.072,125.263 26.072,129.759 25.259,130.572 19.569,130.572 18.198,131.943 18.198,132.604 17.715,133.086 15.81,133.086 15.658,133.239 15.658,134.483 15.81,134.636
  region net NetPP2_2: 239,58.715 238.67,58.385 238.67,57.013 238.162,56.505 238.162,39.919 238.365,39.716 240.676,39.716 240.854,39.894 240.854,58.334 240.473,58.715
  region net NetL1_1: 206.412,22.012 206.005,21.606 206.005,20.158 206.259,19.904 208.825,19.904 210.298,18.431 210.298,14.925 210.526,14.697 212.355,14.697 212.558,14.9 212.558,19.751 210.298,22.012

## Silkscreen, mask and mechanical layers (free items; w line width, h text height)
Top Overlay:
  lines w0.15: 241.47,124.9 246.4,124.9 ; 8.433,25.07 16.078,25.07 16.078,28.956 8.433,28.956 8.433,25.07 ; 16.281,129.692 23.444,129.692 23.444,132.741 16.281,132.741 16.281,129.692
  lines w0.2: 232.3,130 233.3,130
  lines w0.3: 11.786,6.77 12.586,6.77 ; 12.186,6.37 12.186,7.17 ; 62.1,28.2 63.5,28.2 63.5,34.2 62.1,34.2 ; 62.3,28.2 62.3,34.2 ; 211.2,8.4 212.2,8.4 ; 211.7,7.9 211.7,8.9 ; 222.5,8.4 223.5,8.4 ; 242,58.4 242.8,58.4 ; 242.4,58 242.4,58.8
  text "Mouse" at 214.976,132.705 h2 r90
  text "K.B." at 232.777,132.705 h2 r90
  text "RS232/COM1" at 142.1,132.222 h2
  text "VGA" at 178.002,132.222 h2
  text "5V TO ISA" at 16.483,129.873 h1.6
  text "DC12V 3A" at 233.285,117.132 h2
  text "Mouse/TFT" at 123.929,113.667 h2 r90
  text "i386sx inside" at 165.513,64.099 h2.4
  text "ISA/Graphics" at 129.6,52.856 h2
  text "IDE" at 64.2,41 h3 r90
  text "BIOS: F000-FFFF" at 95.393,40.937 h2
  text "ROM: D800-DFFF" at 74.17,40.777 h2
  text "5V TO USB" at 8.594,27.715 h1.6
  text "RJ45" at 39.014,8.201 h2
  text "SPK" at 7.6,6.122 h2
  text "BOOK 386SX" at 65.8,1.048 h4
  text "Keyboard" at 183.8,0.776 h2
  text "Rev. 0.5" at 88.8,0.733 h1.6
Mechanical 1:
  circle w0.15: c121.3,66.6 r5
  lines w0.15: 0.1,1 ccw(c1.1,1) 1.1,0 242.3,0 ccw(c242.3,1) 243.3,1 243.3,61.2 ccw(c242.3,61.2) 242.3,62.2 232.1,62.2 cw(c232.1,63.2) 231.1,63.2 231.1,101.8 cw(c232.1,101.8) 232.1,102.8 242.3,102.8 ccw(c242.3,103.8) 243.3,103.8 243.3,123.9 cw(c243.3,124.9) 243.3,125.9 243.3,136 ccw(c242.3,136) 242.3,137 235.9,137 cw(c235.9,138) 234.9,138 234.9,141.8 ccw(c233.9,141.8) 233.9,142.8 128.7,142.8 ccw(c128.7,141.8) 127.7,141.8 127.7,138.4 cw(c126.7,138.4) 126.7,137.4 115.9,137.4 cw(c115.9,138.4) 114.9,138.4 114.9,141.8 ccw(c113.9,141.8) 113.9,142.8 8.3,142.8 ccw(c8.3,141.8) 7.3,141.8 7.3,138 cw(c6.3,138) 6.3,137 1.1,137 ccw(c1.1,136) 0.1,136 0.1,72 ccw(c1.1,72) 1.1,71 4.7,71 cw(c4.7,70) 5.7,70 5.7,63.2 cw(c4.7,63.2) 4.7,62.2 1.1,62.2 ccw(c1.1,61.2) 0.1,61.2 0.1,1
